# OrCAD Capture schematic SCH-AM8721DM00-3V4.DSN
size Custom
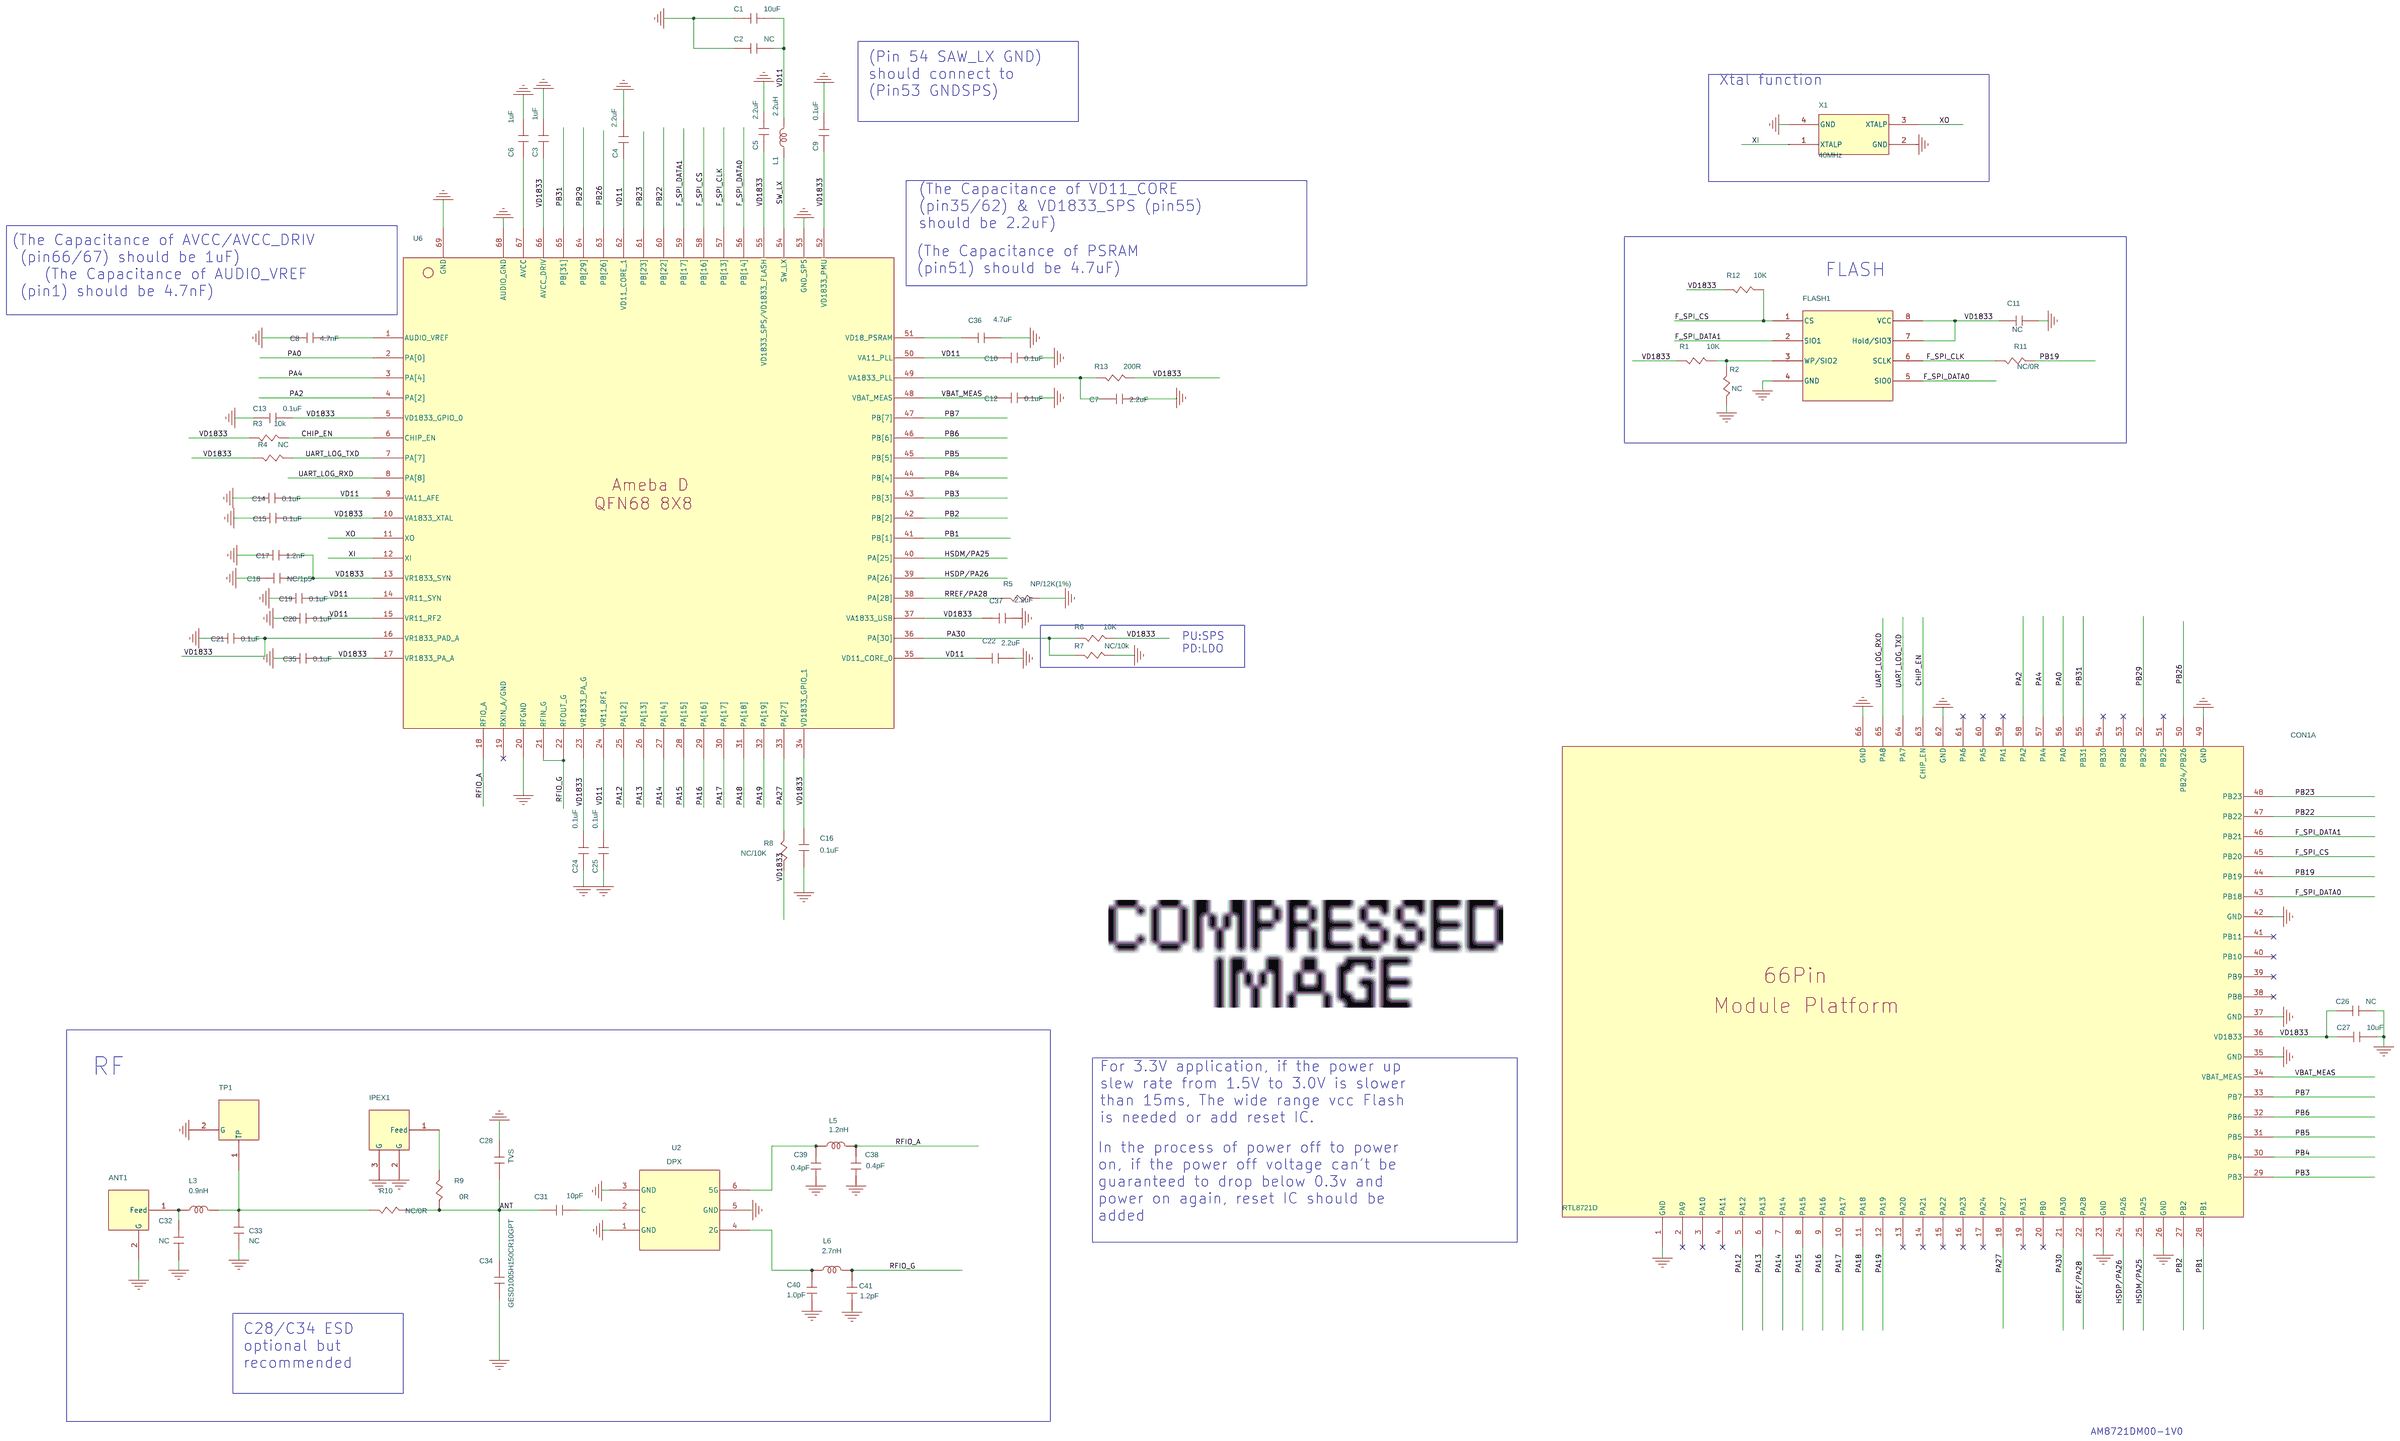
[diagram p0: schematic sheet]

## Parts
ANT1  TP  [8721D_PANT2]
C1  10uF  [C0603]
C2  NC  [C0402]
C3  1uF  [C0402]
C4  2.2uF  [C0402]
C5  2.2uF  [C0402]
C6  1uF  [C0402]
C7  2.2uF  [C0402]
C8  4.7nF  [C0402]
C9  0.1uF  [C0402]
C10  0.1uF  [C0402]
C11  NC  [C0402]
C12  0.1uF  [C0402]
C13  0.1uF  [C0402]
C14  0.1uF  [C0402]
C15  0.1uF  [C0402]
C16  0.1uF  [C0402]
C17  1.2nF  [C0402]
C18  NC/1p5  [C0402]
C19  0.1uF  [C0402]
C20  0.1uF  [C0402]
C21  0.1uF  [C0402]
C22  2.2uF  [C0402]
C24  0.1uF  [C0402]
C25  0.1uF  [C0402]
C26  NC  [C0402]
C27  10uF  [C0603]
C28  TVS  [C0201]
C31  10pF  [C0402]
C32  NC  [C0201]
C33  NC  [C0201]
C34  GESD1005H150CR10GPT  [C0402]
C35  0.1uF  [C0402]
C36  4.7uF  [C0402]
C37  2.2uF  [C0402]
C38  0.4pF  [C0402]
C39  0.4pF  [C0402]
C40  1.0pF  [C0402]
C41  1.2pF  [C0402]
CON1  RTL8721D  [MODULE66-27X37]  (section A)
FLASH1  NC  [SOIC-8P]
IPEX1  TP  [IPEX-0.7X2.2-1.35]
L1  2.2uH  [L2016]
L3  0.9nH  [L0201]
L5  1.2nH  [L0402]
L6  2.7nH  [L0402]
R1  10K  [R0402]
R2  NC  [R0402]
R3  10k  [R0402]
R4  NC  [R0402]
R5  NP/12K(1%)  [R0402]
R6  10K  [R0402]
R7  NC/10k  [R0402]
R8  NC/10K  [R0402]
R9  0R  [R0201]
R10  NC/0R  [R0201]
R11  NC/0R  [R0201]
R12  10K  [R0402]
R13  200R  [R0402]
TP1  TP  [J2]
U2  DPX  [DPX1608-6-0.5-0.25X0.4_1]
U6  RL5760_001  [68LD-MQFN-0.4-8X8_BD1035]
X1  40MHz  [XTAL-2016]

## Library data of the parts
ANT1 = TP_2
C1-C22 C24-C28 C31-C41 = C_402
CON1 = 8723BS_74
FLASH1 = 9346_1
IPEX1 = TP_3
L1 L3 L5 L6 = L0402_1.7NH_ACX
R1-R13 = R0402_1.06K_WALSIN
TP1 = TP_4
U2 = 9346_17
U6 = RL5760_42
X1 = 9346_0

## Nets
GND: ANT1.2(G) C1.2 C2.2 C3.2 C4.2 C5.2 C6.2 C7.2 C8.1 C9.2 C10.2 C11.2 C12.2 C13.1 C14.1 C15.1 C16.1 C17.1 C18.2 C19.2 C20.2 C21.1 C22.2 C24.2 C25.2 C26.1 C27.2 C28.1 C32.1 C33.1 C34.2 C35.1 C36.2 C37.2 C38.1 C39.1 C40.1 C41.1 CON1.1(GND) CON1.23(GND) CON1.26(GND) CON1.35(GND) CON1.37(GND) CON1.42(GND) CON1.49(GND) CON1.62(GND) CON1.66(GND) FLASH1.4(GND) IPEX1.2(G) IPEX1.3(G) R2.2 R5.1 R7.2 TP1.2(G) U2.1(GND) U2.3(GND) U2.5(GND) U6.20(RFGND) U6.53(GND_SPS) U6.68(AUDIO_GND) U6.69(GND) X1.2(GND) X1.4(GND)
VBAT_MEAS: C12.1 CON1.34(VBAT_MEAS) U6.48(VBAT_MEAS)
ANT: C28.2 C31.1 C34.1 R9.1 R10.1
CHIP_EN: CON1.63(CHIP_EN) R3.1 U6.6(CHIP_EN)
F_SPI_CLK: FLASH1.6(SCLK) R11.1 U6.57(PB[13])
F_SPI_CS: CON1.45(PB20) FLASH1.1(CS) R12.1 U6.58(PB[16])
F_SPI_DATA0: CON1.43(PB18) FLASH1.5(SIO0) U6.56(PB[14])
F_SPI_DATA1: CON1.46(PB21) FLASH1.2(SIO1) U6.59(PB[17])
HSDM/PA25: CON1.25(PA25) U6.40(PA[25])
HSDP/PA26: CON1.24(PA26) U6.39(PA[26])
PA0: CON1.56(PA0) U6.2(PA[0])
PA2: CON1.58(PA2) U6.4(PA[2])
PA4: CON1.57(PA4) U6.3(PA[4])
PA12: CON1.5(PA12) U6.25(PA[12])
PA13: CON1.6(PA13) U6.26(PA[13])
PA14: CON1.7(PA14) U6.27(PA[14])
PA15: CON1.8(PA15) U6.28(PA[15])
PA16: CON1.9(PA16) U6.29(PA[16])
PA17: CON1.10(PA17) U6.30(PA[17])
PA18: CON1.11(PA18) U6.31(PA[18])
PA19: CON1.12(PA19) U6.32(PA[19])
PA27: CON1.18(PA27) R8.2 U6.33(PA[27])
PA30: CON1.21(PA30) R6.2 R7.1 U6.36(PA[30])
PB1: CON1.28(PB1) U6.41(PB[1])
PB2: CON1.27(PB2) U6.42(PB[2])
PB3: CON1.29(PB3) U6.43(PB[3])
PB4: CON1.30(PB4) U6.44(PB[4])
PB5: CON1.31(PB5) U6.45(PB[5])
PB6: CON1.32(PB6) U6.46(PB[6])
PB7: CON1.33(PB7) U6.47(PB[7])
PB19: CON1.44(PB19) R11.2
PB22: CON1.47(PB22) U6.60(PB[22])
PB23: CON1.48(PB23) U6.61(PB[23])
PB26: CON1.50(PB24/PB26) U6.63(PB[26])
PB29: CON1.52(PB29) U6.64(PB[29])
PB31: CON1.55(PB31) U6.65(PB[31])
RFIO_A: C38.2 L5.2 U6.18(RFIO_A)
RFIO_G: C41.2 L6.2 U6.21(RFIN_G) U6.22(RFOUT_G)
RREF/PA28: CON1.22(PA28) R5.2 U6.38(PA[28])
SW_LX: L1.1 U6.54(SW_LX)
UART_LOG_RXD: CON1.65(PA8) U6.8(PA[8])
UART_LOG_TXD: CON1.64(PA7) R4.1 U6.7(PA[7])
VD11: C1.1 C2.1 C4.1 C10.1 C14.2 C19.1 C20.1 C22.1 C25.1 L1.2 U6.9(VA11_AFE) U6.14(VR11_SYN) U6.15(VR11_RF2) U6.24(VR11_RF1) U6.35(VD11_CORE_0) U6.50(VA11_PLL) U6.62(VD11_CORE_1)
VD1833: C3.1 C5.1 C9.1 C11.1 C13.2 C15.2 C16.2 C17.2 C18.1 C21.2 C24.1 C26.2 C27.1 C35.2 C37.1 CON1.36(VD1833) FLASH1.7(Hold/SIO3) FLASH1.8(VCC) R1.2 R3.2 R4.2 R6.1 R8.1 R12.2 R13.1 U6.5(VD1833_GPIO_0) U6.10(VA1833_XTAL) U6.13(VR1833_SYN) U6.16(VR1833_PAD_A) U6.17(VR1833_PA_A) U6.23(VR1833_PA_G) U6.34(VD1833_GPIO_1) U6.37(VA1833_USB) U6.52(VD1833_PMU) U6.55(VD1833_SPS/VD1833_FLASH) U6.66(AVCC_DRIV)
XI: U6.12(XI) X1.1(XTALP)
XO: U6.11(XO) X1.3(XTALP)
N17828843: ANT1.1(Feed) C32.2 L3.1
N17998439: C33.2 L3.2 R10.2 TP1.1(TP)
N17999458: IPEX1.1(Feed) R9.2
N18208580: C39.2 L5.1 U2.6(5G)
N18211814: C31.2 U2.2(C)
N18227200: FLASH1.3(WP/SIO2) R1.1 R2.1
N18246899: C40.2 L6.1 U2.4(2G)
N18295758: C6.1 U6.67(AVCC)
N18296339: C8.2 U6.1(AUDIO_VREF)
N18325049: C36.1 U6.51(VD18_PSRAM)
N18344735: C7.1 R13.2 U6.49(VA1833_PLL)

Not connected (* = marked no-connect by the designer): CON1 2(PA9)* 3(PA10)* 4(PA11)* 13(PA20)* 14(PA21)* 15(PA22)* 16(PA23)* 17(PA24)* 19(PA31)* 20(PB0)* 38(PB8)* 39(PB9)* 40(PB10)* 41(PB11)* 51(PB25)* 53(PB28)* 54(PB30)* 59(PA1)* 60(PA5)* 61(PA6)*; U6 19(RXIN_A/GND)*

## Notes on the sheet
- (Pin 54 SAW_LX GND)
  should connect to
  (Pin53 GNDSPS)
- Xtal function
- (The Capacitance of VD11_CORE
  (pin35/62) & VD1833_SPS (pin55)
  should be 2.2uF)
- (The Capacitance of AVCC/AVCC_DRIV
   (pin66/67) should be 1uF)
      (The Capacitance of AUDIO_VREF
   (pin1) should be 4.7nF)
- (The Capacitance of PSRAM
  (pin51) should be 4.7uF)
- FLASH
- PU:SPS
  PD:LDO
- RF
- For 3.3V application, if the power up
  slew rate from 1.5V to 3.0V is slower
  than 15ms, The wide range vcc Flash
  is needed or add reset IC.
- In the process of power off to power
  on, if the power off voltage can't be
  guaranteed to drop below 0.3v and
  power on again, reset IC should be
  added
- C28/C34 ESD
  optional but
  recommended
- AM8721DM00-1V0
